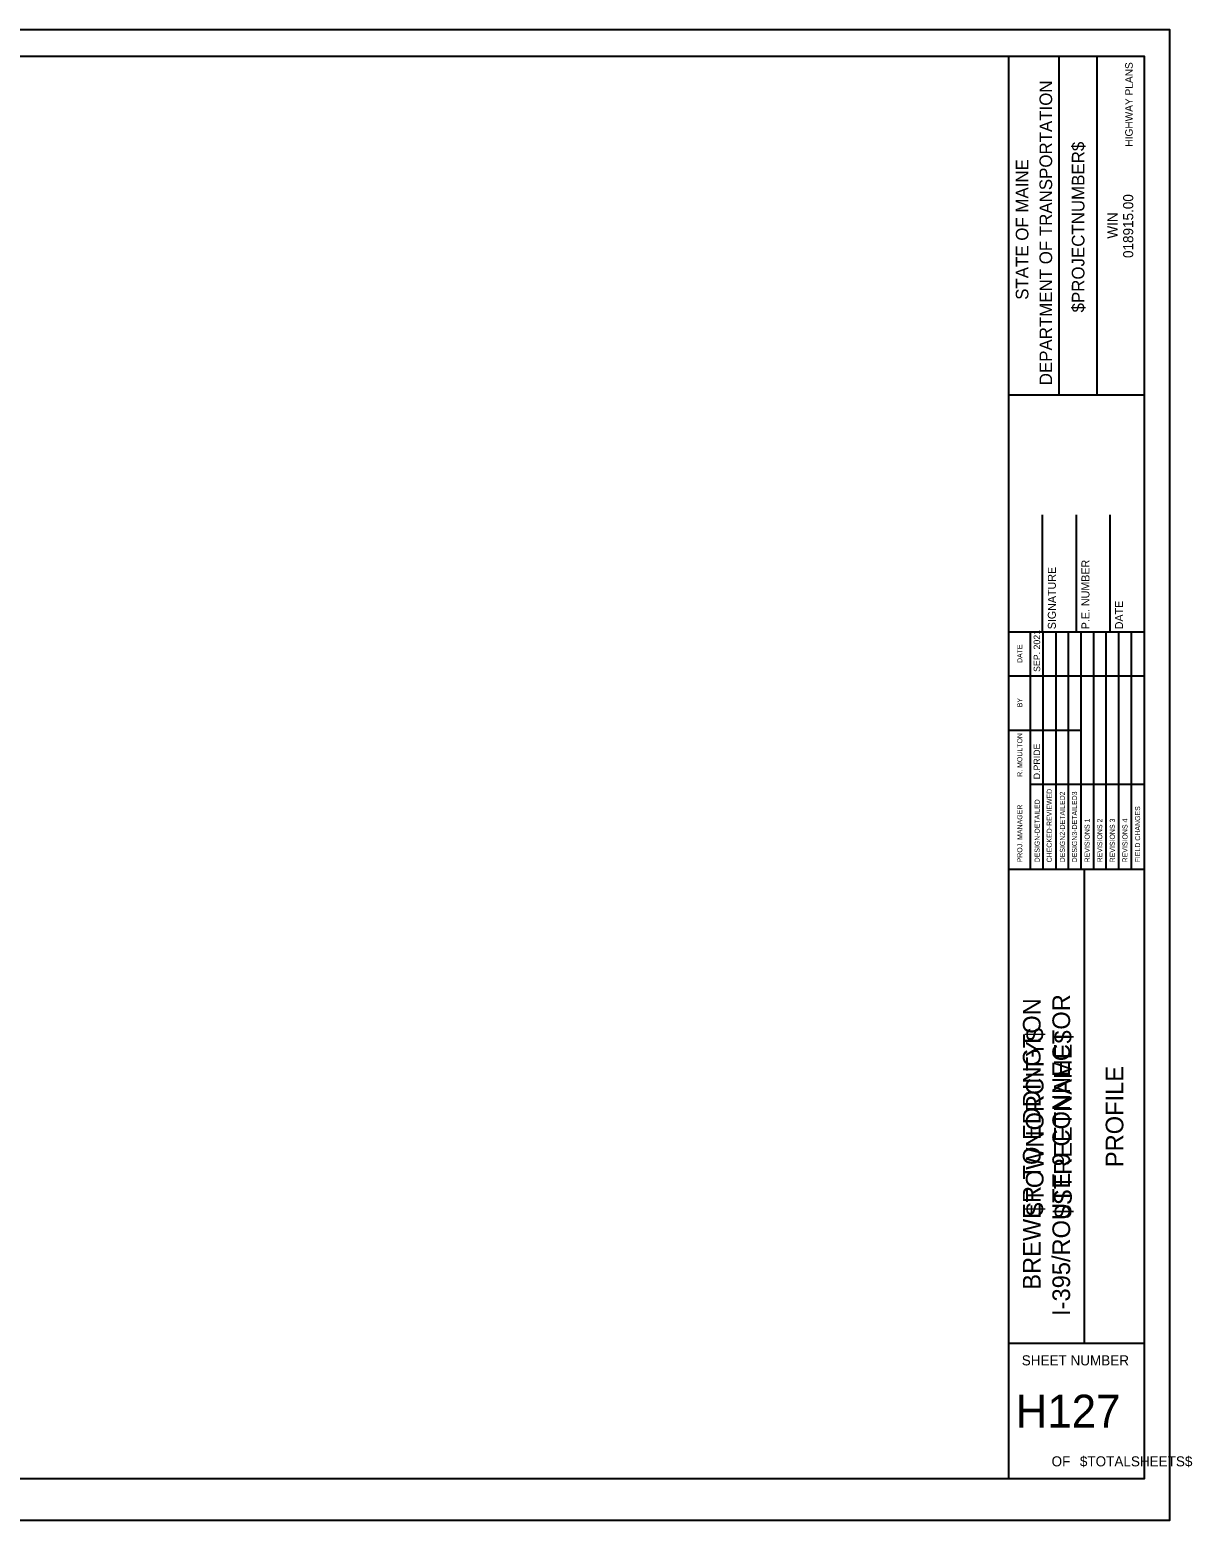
# Model space of a CAD drawing. Extents: x 1089072 to 1089930, y 734712 to 735262.
# Drawn here: x 1089501 to 1089930, y 734712 to 735262 of the extents above; entities that cross this region are included whole.
import ezdxf

# ---------------------------------------------------------------- set-up
doc = ezdxf.new("R2010")
doc.units = 0
for name, color, linetype in [('H_V ANNOTATION', 7, 'Continuous'), ('MAJOR', 7, 'Continuous'), ('S_Roadway_Centerline', 7, 'Continuous')]:
    doc.layers.add(name, color=color, linetype=linetype)

msp = doc.modelspace()

# ---------------------------------------------------------------- linework, layer by layer
at = {"layer": 'H_V ANNOTATION'}
for p, q in [((1089862.06, 734726.84), (1089862.06, 735251.84)), ((1089880.7, 735126.82), (1089880.7, 735251.82)), ((1089894.68, 735126.82), (1089894.68, 735251.82)), ((1089862.06, 735126.81), (1089912.06, 735126.81)), ((1089874.56, 735039.35), (1089874.56, 735082.59)), ((1089887.06, 735039.35), (1089887.06, 735082.59)), ((1089899.56, 735039.35), (1089899.56, 735082.59)), ((1089862.06, 735039.35), (1089912.06, 735039.35)), ((1089862.06, 734951.85), (1089912.06, 734951.85)), ((1089890.01, 734776.85), (1089890.01, 734951.85)), ((1089862.06, 734776.85), (1089912.06, 734776.85))]:
    msp.add_line(p, q, dxfattribs=at)
msp.add_lwpolyline([(1089112.06, 735251.84), (1089912.06, 735251.84), (1089912.06, 734726.84), (1089112.06, 734726.84)], close=True, dxfattribs=at)
for points in [[(1089870.13, 735023.1), (1089870.13, 735039.35)], [(1089874.79, 734951.87), (1089874.79, 735039.35)], [(1089879.45, 735039.35), (1089879.45, 734951.87)], [(1089884.11, 734951.87), (1089884.11, 735039.35)], [(1089888.77, 734951.87), (1089888.77, 735039.35)], [(1089893.43, 734951.87), (1089893.43, 735039.35)], [(1089898.09, 734951.87), (1089898.09, 735039.35)], [(1089902.74, 734951.87), (1089902.74, 735039.35)], [(1089907.4, 734951.87), (1089907.4, 735039.35)], [(1089870.14, 734951.87), (1089870.14, 735035.82)], [(1089862.06, 735023.1), (1089912.06, 735023.1)], [(1089862.06, 735003.1), (1089870.14, 735003.1)], [(1089870.13, 735003.1), (1089888.76, 735003.1)], [(1089870.13, 734983.1), (1089912.06, 734983.1)]]:
    msp.add_lwpolyline(points, dxfattribs=at)
at = {"layer": 'MAJOR'}
msp.add_lwpolyline([(1089071.59, 734711.54), (1089921.59, 734711.54), (1089921.59, 735261.54), (1089071.59, 735261.54)], close=True, dxfattribs=at)

# ---------------------------------------------------------------- texts
at = {"layer": 'H_V ANNOTATION'}
for s, height, p in [('DEPARTMENT OF TRANSPORTATION', 4.6588, (1089878.09, 735130.37)), ('$PROJECTNUMBER$', 4.6588, (1089890.02, 735157.24)), ('STATE OF MAINE', 4.6588, (1089869.33, 735161.9)), ('018915.00', 3.726, (1089908.03, 735177.33)), ('WIN', 3.726, (1089902.24, 735184.49)), ('P.E. NUMBER', 2.9528, (1089891.86, 735040.32)), ('SIGNATURE', 2.953, (1089879.46, 735040.32)), ('DATE', 2.953, (1089904.26, 735040.32)), ('SEP. 2021', 2.423, (1089873.67, 735024.58)), ('DATE', 1.857, (1089867.08, 735027.88)), ('BY', 1.857, (1089867.08, 735011.53)), ('R. MOULTON', 1.864, (1089867.08, 734985.87)), ('D.PRIDE', 2.423, (1089873.67, 734984.97)), ('DESIGN-DETAILED', 1.8637, (1089873.49, 734954.29)), ('CHECKED-REVIEWED', 1.8637, (1089877.96, 734954.29)), ('DESIGN2-DETAILED2', 1.8637, (1089882.81, 734954.29)), ('DESIGN3-DETAILED3', 1.8637, (1089887.28, 734954.29)), ('PROJ. MANAGER', 1.8637, (1089867.08, 734954.29)), ('FIELD CHANGES', 1.8637, (1089910.57, 734954.29)), ('REVISIONS 1', 1.8637, (1089891.94, 734954.29)), ('REVISIONS 2', 1.8637, (1089896.6, 734954.29)), ('REVISIONS 3', 1.8637, (1089901.25, 734954.29)), ('REVISIONS 4', 1.8637, (1089905.91, 734954.29)), ('I-395/ROUTE 9 CONNECTOR', 6.5214, (1089884.71, 734786.93)), ('BREWER TO EDDINGTON', 6.5214, (1089873.82, 734796.6)), ('PROFILE', 6.521, (1089904.38, 734841.84))]:
    msp.add_text(s, height=height, rotation=90, dxfattribs=at).set_placement(p)
for s, height, p in [('SHEET NUMBER', 3.7264, (1089866.88, 734768.67)), ('H127', 12.097, (1089864.63, 734745.75)), ('OF', 3.726, (1089877.89, 734731.4)), ('$TOTALSHEETS$', 3.7264, (1089888.34, 734731.4))]:
    msp.add_text(s, height=height, dxfattribs=at).set_placement(p)
at = {"layer": 'S_Roadway_Centerline'}
for s, height, p in [('HIGHWAY PLANS', 2.795, (1089907.85, 735218.42)), ('$TOWNORCITY$', 6.5214, (1089874.92, 734823.9)), ('$STREETNAME$', 6.5214, (1089885.35, 734823))]:
    msp.add_text(s, height=height, rotation=90, dxfattribs=at).set_placement(p)

doc.saveas('drawing.dxf')
